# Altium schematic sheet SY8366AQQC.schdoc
size 127 x 101 mm
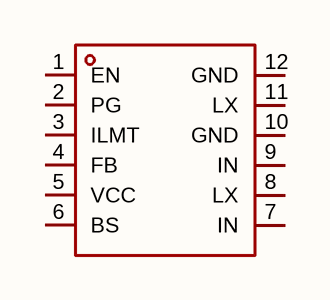
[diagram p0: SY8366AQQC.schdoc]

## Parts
U?  sy8366aqqc  [QFN-12_L3.0-W3.0-P0.45-TL_SY8366A]  (value not drawn)

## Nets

Not connected (* = marked no-connect by the designer): U? 1(EN) 2(PG) 3(ILMT) 4(FB) 5(VCC) 6(BS) 7(IN) 8(LX) 9(IN) 10(GND) 11(LX) 12(GND)

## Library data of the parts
U? = sy8366aqqc: 功能类型:降压型;工作电压:4V~28V;输出电压:600mV~28V;输出电流:6A;输出类型:可调;; Manufacturer: Silergy(矽力杰); AddInBom: yes; ModelId: 159ef8c079274b5d9aba7285ad323130; ModelTransform: 118.8974,118.5037,0,0,0,0,0,-10.63,0; Function: 降压型; Voltage - Supply: 4V~28V; Output Current: 6A; Frequency - Switching: 800kHz; Synchronous Rectifier: 是; Number of Outputs: 1; Topology: 降压式; Quiescent Current: 100uA; Switch tube (built-in/external): 内置; Output Type: 可调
